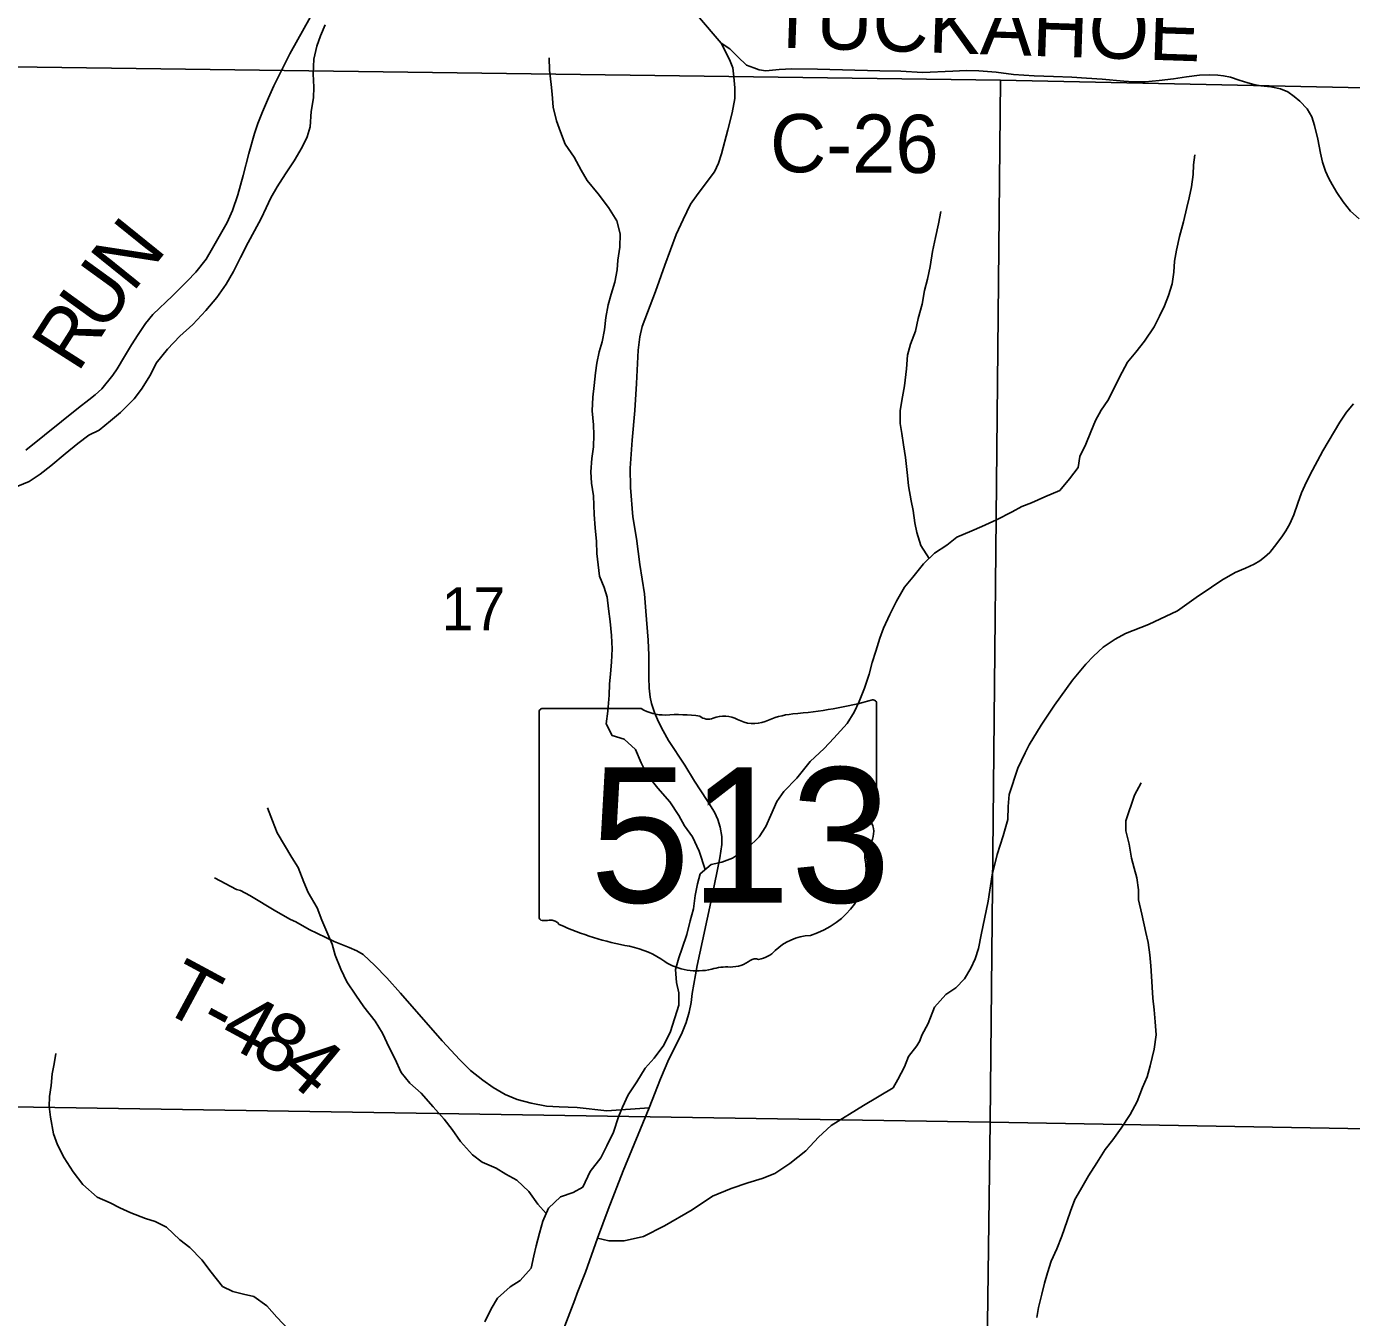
# Model space of a CAD drawing. Extents: x 0 to 191, y 0 to 55.
# Drawn here: x 148.062 to 148.709, y 23.985 to 24.615 of the extents above; entities that cross this region are included whole.
import ezdxf

# ---------------------------------------------------------------- set-up
doc = ezdxf.new("R2010")
doc.units = 0
for name, color, linetype in [('GM_X_Corporation', 7, 'Continuous'), ('GM_X_County_Road', 7, 'Continuous'), ('GM_X_County_Road_Text', 7, 'Continuous'), ('GM_X_Minor_River', 7, 'Continuous'), ('GM_X_Section_Text', 7, 'Continuous'), ('GM_X_State_Location', 7, 'Continuous'), ('GM_X_State_Route', 7, 'Continuous'), ('GM_X_State_Shield', 7, 'Continuous'), ('GM_X_Township_Road', 7, 'Continuous'), ('GM_X_Township_Road_Text', 7, 'Continuous')]:
    doc.layers.add(name, color=color, linetype=linetype)

msp = doc.modelspace()

# ---------------------------------------------------------------- linework, layer by layer
at = {"layer": 'GM_X_Corporation'}
for points in [[(148.03126, 24.59594), (148.53803, 24.58915), (148.53297, 24.08032), (148.0241, 24.08841)], [(148.53803, 24.58915), (149.0475, 24.57841), (149.03882, 24.07143), (148.53297, 24.08032)], [(148.0241, 24.08841), (148.53297, 24.08032), (148.52633, 23.57659), (148.01656, 23.58107)], [(148.53297, 24.08032), (149.03882, 24.07143), (149.03316, 23.56525), (148.52633, 23.57659)]]:
    msp.add_lwpolyline(points, close=True, dxfattribs=at)
at = {"layer": 'GM_X_County_Road'}
for points in [[(148.20115, 24.62009), (148.19102, 24.60199), (148.18321, 24.58628), (148.18065, 24.58049), (148.17763, 24.57367), (148.1754, 24.56792), (148.17374, 24.563), (148.17097, 24.55337), (148.16825, 24.54258), (148.16568, 24.5332), (148.16304, 24.52555), (148.16047, 24.51956), (148.15332, 24.50703), (148.15014, 24.50174), (148.14518, 24.49542), (148.14096, 24.49091), (148.13369, 24.48376), (148.1241, 24.47471), (148.12058, 24.47028), (148.11699, 24.46499), (148.11376, 24.45986), (148.11029, 24.45412), (148.10665, 24.44821), (148.10454, 24.44507), (148.09913, 24.43849), (148.09595, 24.43552), (148.09293, 24.43304), (148.08788, 24.42911), (148.07122, 24.4158), (148.06205, 24.40852)], [(148.40171, 24.60717), (148.40583, 24.60447), (148.40976, 24.6005), (148.41402, 24.59651), (148.41753, 24.59507), (148.42014, 24.5941), (148.42352, 24.59369), (148.42997, 24.59427), (148.4361, 24.59457), (148.44872, 24.59452), (148.4792, 24.59372), (148.48932, 24.59347), (148.49992, 24.59279), (148.51485, 24.59342), (148.52129, 24.59376), (148.52747, 24.59372), (148.53602, 24.593), (148.5444, 24.59194), (148.55457, 24.59126), (148.56392, 24.59097), (148.57294, 24.59059), (148.58009, 24.59012), (148.58763, 24.58965), (148.59822, 24.5886), (148.603, 24.5883), (148.60872, 24.58826), (148.61557, 24.58893), (148.62252, 24.58974), (148.62895, 24.59067), (148.63526, 24.59148), (148.64009, 24.59177), (148.64424, 24.5916), (148.64695, 24.59126), (148.65042, 24.5905), (148.65465, 24.58915), (148.65884, 24.58783), (148.66172, 24.58703), (148.66524, 24.58627), (148.67006, 24.58584), (148.6748, 24.58483), (148.67832, 24.58339), (148.68154, 24.58119), (148.68425, 24.57882), (148.6878, 24.57518), (148.69005, 24.57124), (148.69144, 24.567), (148.69305, 24.56031), (148.69424, 24.5535), (148.6953, 24.54901), (148.69682, 24.54465), (148.69834, 24.54118), (148.69995, 24.53809), (148.70232, 24.53432), (148.70533, 24.52966), (148.70897, 24.52517), (148.71325, 24.52136)]]:
    msp.add_lwpolyline(points, dxfattribs=at)
at = {"layer": 'GM_X_Minor_River'}
for points in [[(148.05816, 24.39089), (148.06365, 24.39319), (148.06915, 24.39682), (148.07426, 24.40083), (148.08126, 24.40674), (148.08751, 24.4117), (148.09281, 24.41571), (148.09793, 24.41819), (148.10342, 24.42277), (148.10834, 24.42678), (148.11497, 24.43345), (148.11856, 24.43821), (148.1229, 24.44525), (148.12573, 24.45096), (148.13122, 24.45782), (148.13728, 24.46411), (148.14371, 24.46983), (148.14995, 24.47669), (148.15544, 24.48298), (148.15998, 24.48945), (148.16357, 24.49574), (148.16696, 24.50259), (148.17074, 24.50982), (148.17376, 24.51553), (148.17697, 24.52162), (148.17942, 24.52676), (148.18169, 24.5317), (148.1849, 24.53703), (148.18887, 24.54332), (148.19321, 24.54979), (148.19699, 24.55645), (148.19944, 24.5614), (148.20095, 24.56635), (148.2015, 24.57376), (148.20262, 24.58041), (148.2028, 24.58573), (148.2024, 24.59219), (148.20276, 24.59941), (148.20426, 24.60568), (148.20596, 24.61082), (148.20822, 24.61615)], [(148.3939, 24.20374), (148.39084, 24.21263), (148.3876, 24.21965), (148.38379, 24.22514), (148.38093, 24.23008), (148.37655, 24.23671), (148.37065, 24.24353), (148.36551, 24.24997), (148.36265, 24.25585), (148.35978, 24.2623), (148.35427, 24.26742), (148.34838, 24.26911), (148.34552, 24.2748), (148.34626, 24.28107), (148.347, 24.28886), (148.34718, 24.29418), (148.34755, 24.29931), (148.3481, 24.30501), (148.34846, 24.31148), (148.34807, 24.31793), (148.34748, 24.32477), (148.3467, 24.33104), (148.34593, 24.33674), (148.34459, 24.34148), (148.3423, 24.34699), (148.34152, 24.35249), (148.34094, 24.358), (148.34074, 24.36389), (148.34015, 24.37054), (148.33956, 24.377), (148.33935, 24.38612), (148.33838, 24.39238), (148.33799, 24.39789), (148.33854, 24.40435), (148.33929, 24.41006), (148.33946, 24.41595), (148.33926, 24.42089), (148.33867, 24.42772), (148.33903, 24.43438), (148.33959, 24.44008), (148.34033, 24.44616), (148.34089, 24.45091), (148.34201, 24.45643), (148.34352, 24.46137), (148.34464, 24.46727), (148.34538, 24.47316), (148.3465, 24.47943), (148.34801, 24.48457), (148.3497, 24.49046), (148.35082, 24.49655), (148.35119, 24.5013), (148.35212, 24.50757), (148.3523, 24.51403), (148.35076, 24.52049), (148.34657, 24.52693), (148.34162, 24.53357), (148.33629, 24.5402), (148.33324, 24.54513), (148.32981, 24.55158), (148.32543, 24.55783), (148.32314, 24.5639), (148.32123, 24.56922), (148.31969, 24.57586), (148.31911, 24.58232), (148.31871, 24.58707), (148.31775, 24.59391), (148.31773, 24.59999)], [(148.31728, 24.0384), (148.32315, 24.04393), (148.32941, 24.04604), (148.33415, 24.04871), (148.33773, 24.05632), (148.34284, 24.06298), (148.34586, 24.06888), (148.34907, 24.07554), (148.35152, 24.08295), (148.3534, 24.08771), (148.35623, 24.0938), (148.36039, 24.10008), (148.36455, 24.10674), (148.3689, 24.11169), (148.37363, 24.11797), (148.37684, 24.12463), (148.38098, 24.13756), (148.38096, 24.14345), (148.37981, 24.14858), (148.37941, 24.15484), (148.38092, 24.16055), (148.38261, 24.1653), (148.38487, 24.17196), (148.38656, 24.17861), (148.38807, 24.1845), (148.389, 24.19097), (148.39012, 24.19667), (148.39144, 24.20161), (148.39674, 24.20619), (148.40205, 24.20735), (148.40717, 24.20926), (148.41455, 24.21422), (148.42023, 24.21975), (148.42344, 24.2247), (148.4259, 24.23022), (148.42891, 24.23688), (148.43232, 24.24183), (148.43856, 24.24831), (148.44518, 24.2565), (148.45199, 24.26279), (148.45672, 24.26793), (148.46316, 24.27498), (148.46656, 24.2805), (148.46901, 24.28583), (148.47165, 24.2923), (148.47391, 24.29915), (148.47541, 24.30485), (148.4771, 24.31037), (148.47917, 24.31665), (148.48087, 24.32159), (148.48408, 24.32825), (148.48728, 24.33472), (148.49125, 24.34157), (148.49522, 24.34653), (148.50052, 24.35301), (148.50582, 24.35815), (148.51188, 24.36216), (148.5168, 24.36598), (148.524, 24.36904), (148.52893, 24.37115), (148.53613, 24.3744), (148.54371, 24.37842), (148.54845, 24.3809), (148.55318, 24.38282), (148.55963, 24.38569), (148.56702, 24.38875), (148.57175, 24.39447), (148.57591, 24.39999), (148.57684, 24.40532), (148.57967, 24.41141), (148.58212, 24.41749), (148.58438, 24.42301), (148.58721, 24.42796), (148.59043, 24.43272), (148.59364, 24.43881), (148.59609, 24.44414), (148.60005, 24.45138), (148.60421, 24.45633), (148.60837, 24.46167), (148.6131, 24.46871), (148.61574, 24.47385), (148.61819, 24.47899), (148.62008, 24.48394), (148.62196, 24.48964), (148.6227, 24.49535), (148.62307, 24.50067), (148.624, 24.50618), (148.6255, 24.51284), (148.62738, 24.51987), (148.62907, 24.52691), (148.6302, 24.53166), (148.63132, 24.53699), (148.63207, 24.54307), (148.63224, 24.54782), (148.63299, 24.55258)], [(148.5032, 24.35562), (148.49917, 24.36193), (148.49725, 24.3682), (148.49629, 24.37294), (148.49533, 24.37902), (148.49437, 24.38377), (148.49321, 24.39099), (148.49262, 24.39611), (148.49165, 24.40485), (148.49069, 24.41112), (148.48991, 24.41663), (148.48914, 24.42156), (148.48912, 24.42783), (148.49025, 24.43449), (148.49118, 24.43981), (148.49211, 24.44818), (148.49266, 24.45483), (148.49416, 24.46015), (148.49661, 24.46662), (148.49792, 24.47271), (148.4998, 24.47974), (148.50092, 24.4864), (148.50243, 24.49191), (148.50374, 24.49819), (148.50486, 24.50541), (148.50636, 24.51226), (148.50786, 24.51891), (148.50898, 24.525)], [(148.61185, 24.15159), (148.61146, 24.15671), (148.61106, 24.16203), (148.6101, 24.16811), (148.60895, 24.17304), (148.60703, 24.18197), (148.60549, 24.18899), (148.60548, 24.19374), (148.6047, 24.19963), (148.60336, 24.20437), (148.60202, 24.20931), (148.60087, 24.21614), (148.59933, 24.2226), (148.59932, 24.22754), (148.60346, 24.24009), (148.60667, 24.24599)], [(148.31621, 24.03586), (148.31216, 24.04029), (148.30778, 24.04654), (148.30188, 24.05203), (148.29656, 24.05505), (148.29181, 24.05788), (148.28497, 24.0609), (148.28022, 24.0645), (148.27432, 24.07094), (148.27032, 24.07681), (148.26633, 24.08193), (148.261, 24.0878), (148.2551, 24.09462), (148.24959, 24.09935), (148.2454, 24.10465), (148.24235, 24.11148), (148.23949, 24.11679), (148.23624, 24.12381), (148.23262, 24.12968), (148.2271, 24.13669), (148.22329, 24.14238), (148.21891, 24.14883), (148.21586, 24.15508), (148.21319, 24.16191), (148.21166, 24.16723), (148.20956, 24.17216), (148.20669, 24.17899), (148.2044, 24.18506), (148.20002, 24.19245), (148.19792, 24.19758), (148.19505, 24.20479), (148.19201, 24.20953), (148.18476, 24.22166), (148.18247, 24.22754), (148.18018, 24.2338)], [(148.55572, 23.98503), (148.55666, 23.98997), (148.55816, 23.99643), (148.55948, 24.00175), (148.56098, 24.00688), (148.56287, 24.01258), (148.56551, 24.01848), (148.56796, 24.02476), (148.5706, 24.03217), (148.57229, 24.03692), (148.57437, 24.04263), (148.5772, 24.04739), (148.58098, 24.05423), (148.58514, 24.06052), (148.58911, 24.06699), (148.59289, 24.07175), (148.59705, 24.07746), (148.60139, 24.08412), (148.60479, 24.0904), (148.60743, 24.09724), (148.6097, 24.10257), (148.6112, 24.10789), (148.61308, 24.11607), (148.61401, 24.1231), (148.61361, 24.12937), (148.61303, 24.13525), (148.61244, 24.14095), (148.61205, 24.14627), (148.61185, 24.15159)], [(148.19031, 23.97913), (148.1846, 23.98519), (148.17984, 23.99068), (148.17338, 23.99522), (148.16844, 23.99634), (148.16313, 23.99765), (148.15819, 24.00011), (148.15267, 24.00712), (148.1481, 24.01318), (148.1422, 24.01924), (148.13726, 24.02302), (148.1308, 24.02908), (148.12529, 24.03191), (148.12054, 24.03341), (148.11332, 24.03605), (148.108, 24.0385), (148.10325, 24.04096), (148.09698, 24.04378), (148.08995, 24.05003), (148.08519, 24.05609), (148.08081, 24.06291), (148.07757, 24.06936), (148.07566, 24.07467), (148.07412, 24.08284), (148.07354, 24.08796), (148.07372, 24.0929), (148.07446, 24.09822), (148.07502, 24.10392), (148.07595, 24.10886), (148.0767, 24.11399)], [(148.2863, 23.98285), (148.28932, 23.98932), (148.29235, 23.99446), (148.2986, 23.99998), (148.30352, 24.00304), (148.30882, 24.00913), (148.31013, 24.01521), (148.31126, 24.01996), (148.31295, 24.02624), (148.31464, 24.03213), (148.31728, 24.0384)]]:
    msp.add_lwpolyline(points, dxfattribs=at)
at = {"layer": 'GM_X_State_Route'}
msp.add_lwpolyline([(148.32067, 23.96905), (148.32691, 23.98526), (148.33021, 23.99369), (148.33129, 23.99685), (148.33539, 24.00709), (148.34125, 24.0238), (148.34646, 24.03774), (148.35378, 24.05663), (148.36651, 24.08735), (148.372, 24.10152), (148.37612, 24.11108), (148.38087, 24.12044), (148.38266, 24.12422), (148.38458, 24.12903), (148.3861, 24.13405), (148.38699, 24.1388), (148.38747, 24.14313), (148.38988, 24.15682), (148.39256, 24.16885), (148.39717, 24.19004), (148.40095, 24.20943), (148.4015, 24.21267), (148.40192, 24.21597), (148.40205, 24.21989), (148.40123, 24.22443), (148.39999, 24.22821), (148.39841, 24.23179), (148.39476, 24.23743), (148.38864, 24.24692), (148.38383, 24.25476), (148.37599, 24.26679), (148.37337, 24.27147), (148.37097, 24.2758), (148.36911, 24.28041), (148.36766, 24.28474), (148.36705, 24.28791), (148.36649, 24.29224), (148.36629, 24.2974), (148.36636, 24.30833), (148.36601, 24.31563), (148.36478, 24.32986), (148.36423, 24.33825), (148.36189, 24.3527), (148.36024, 24.36528), (148.35845, 24.37587), (148.35735, 24.39025), (148.35728, 24.39974), (148.35824, 24.41336), (148.35948, 24.4278), (148.36031, 24.44107), (148.36106, 24.45731), (148.36189, 24.46384), (148.36306, 24.46879), (148.36952, 24.48585), (148.37413, 24.49885), (148.3797, 24.5137), (148.38314, 24.52106), (148.38665, 24.52856), (148.39043, 24.53385), (148.39841, 24.54438), (148.4004, 24.54857), (148.40178, 24.55318), (148.40494, 24.56487), (148.407, 24.5732), (148.40838, 24.58021), (148.40838, 24.58537), (148.4079, 24.5908), (148.40728, 24.59514), (148.40577, 24.59926), (148.40171, 24.60717), (148.39009, 24.62065)], dxfattribs=at)
at = {"layer": 'GM_X_State_Shield'}
for p, q in [((148.47758, 24.23249), (148.47758, 24.28483)), ((148.31279, 24.28063), (148.31279, 24.18057)), ((148.36267, 24.28236), (148.31441, 24.28236)), ((148.47756, 24.2325), (148.47758, 24.23249))]:
    msp.add_line(p, q, dxfattribs=at)
for centre, major_axis, start_param, end_param in [((148.41888, 24.41877), (0.17476, 0), 4.814394, 5.042369), ((148.47575, 24.28505), (0.00183, 0), 6.141152, 7.989035), ((148.31467, 24.28085), (0.00191, 0), 1.712693, 3.28349), ((148.37416, 24.29397), (0.01852, 0), 4.042523, 4.731795), ((148.3803, 24.22618), (0.06648, 0), 1.404758, 1.657858), ((148.39539, 24.28137), (0.00534, 0), 3.836095, 5.185415), ((148.40323, 24.2698), (0.01111, 0), 0.950623, 2.079405), ((148.41757, 24.28566), (0.01336, 0), 4.081561, 5.145723), ((148.44117, 24.25179), (0.03516, 0), 1.699011, 2.107814), ((148.47562, 24.23229), (0.00196, 0), 5.05454, 6.418171), ((148.47715, 24.22865), (0.00284, 0), 1.883978, 3.671073), ((148.45909, 24.22203), (0.01704, 0), 5.934695, 6.695948), ((148.48415, 24.21059), (0.0124, 0), 2.387724, 3.262537), ((148.42867, 24.20393), (0.04371, 0), 5.101752, 6.440018), ((148.31469, 24.18035), (0.00193, 0), 3.00124, 4.508301), ((148.31498, 24.19059), (0.0147, 0), 4.665946, 4.897461), ((148.31799, 24.1748), (0.0053, 0), 0.519207, 1.627899), ((148.3849, 24.2647), (0.1262, 0), 4.195997, 4.488961), ((148.4471, 24.15248), (0.02394, 0), 1.647645, 2.488434), ((148.34728, 24.13562), (0.03949, 0), 0.823519, 1.323587), ((148.41676, 24.17088), (0.01412, 0), 4.937069, 5.64225), ((148.38998, 24.1743), (0.02506, 0), 4.026481, 4.996735), ((148.40446, 24.13971), (0.02059, 0), 1.495662, 1.94098), ((148.40629, 24.16681), (0.01335, 0), 4.691044, 5.507374), ((148.41837, 24.15712), (0.00376, 0), 1.147584, 2.315152)]:
    msp.add_ellipse(centre, major_axis=major_axis, ratio=0.8, start_param=start_param, end_param=end_param, dxfattribs=at)
at = {"layer": 'GM_X_Township_Road'}
for points in [[(148.48559, 24.09721), (148.48789, 24.10116), (148.4911, 24.10741), (148.49315, 24.11242), (148.49726, 24.11768), (148.49866, 24.12007), (148.49964, 24.12294), (148.50269, 24.12853), (148.50589, 24.13651), (148.51132, 24.14267), (148.51628, 24.14603), (148.52042, 24.1504), (148.5235, 24.15555), (148.52567, 24.1601), (148.52732, 24.16525), (148.52856, 24.17178), (148.5321, 24.18824), (148.53394, 24.20107), (148.53638, 24.21105), (148.53928, 24.22025), (148.54162, 24.2282), (148.54176, 24.2345), (148.54226, 24.24029), (148.54649, 24.25317), (148.55004, 24.26076), (148.55201, 24.26466), (148.5579, 24.27414), (148.56443, 24.28402), (148.57316, 24.29616), (148.57969, 24.30407), (148.58346, 24.30789), (148.58825, 24.31235), (148.59409, 24.31619), (148.59905, 24.31892), (148.61036, 24.32343), (148.62457, 24.32996), (148.63368, 24.33649), (148.64108, 24.34155), (148.64609, 24.34504), (148.65271, 24.34872), (148.65777, 24.35088), (148.66186, 24.35286), (148.66467, 24.35451), (148.66692, 24.35626), (148.66954, 24.35847), (148.67189, 24.36136), (148.67538, 24.36619), (148.67741, 24.36909), (148.67938, 24.37254), (148.68131, 24.37686), (148.6832, 24.38252), (148.68509, 24.38767), (148.68665, 24.39125), (148.68913, 24.39631), (148.69548, 24.40822), (148.70371, 24.42211), (148.70697, 24.42698), (148.71038, 24.43103)], [(148.15417, 24.19973), (148.16494, 24.19398), (148.16689, 24.19341), (148.17142, 24.19099), (148.18413, 24.18337), (148.19142, 24.17933), (148.19401, 24.17827), (148.20041, 24.17447), (148.21272, 24.16864), (148.22, 24.16572), (148.22381, 24.1641), (148.22689, 24.16232), (148.23255, 24.1569), (148.23838, 24.1509), (148.2451, 24.14329), (148.26543, 24.12014), (148.27401, 24.11082), (148.27919, 24.10564), (148.28527, 24.10087), (148.29029, 24.0973), (148.29612, 24.09382), (148.30211, 24.09147), (148.30883, 24.08961), (148.31628, 24.08823), (148.32259, 24.08783), (148.33126, 24.08759), (148.34583, 24.08589), (148.36651, 24.08735)], [(148.34125, 24.0238), (148.34687, 24.02245), (148.35427, 24.02245), (148.36372, 24.02451), (148.374, 24.02985), (148.38756, 24.03766), (148.39743, 24.04423), (148.40647, 24.04793), (148.41469, 24.05081), (148.42168, 24.05287), (148.42784, 24.05533), (148.43524, 24.06026), (148.44305, 24.06643), (148.44921, 24.073), (148.45538, 24.07876), (148.4712, 24.0885), (148.48559, 24.09721)]]:
    msp.add_lwpolyline(points, dxfattribs=at)

# ---------------------------------------------------------------- texts
at = {"layer": 'GM_X_County_Road_Text'}
for s, height, rotation, p in [('TUCKAHOE', 0.028409, 358.12412, (148.42455, 24.60519)), ('C-26', 0.028409, 359.6571, (148.42544, 24.54423)), ('N', 0.02841, 51.12172, (148.11419, 24.48498)), ('U', 0.02841, 54.09475, (148.09977, 24.46504)), ('R', 0.02841, 57.49318, (148.08748, 24.44573))]:
    msp.add_text(s, height=height, rotation=rotation, dxfattribs=at).set_placement(p)
at = {"layer": 'GM_X_Section_Text'}
msp.add_text('17', height=0.020928, rotation=0.00001, dxfattribs=at).set_placement((148.26511, 24.32054))
at = {"layer": 'GM_X_State_Location'}
for s in ['s', 'r']:
    msp.add_text(s, height=0.0000947, dxfattribs=at).set_placement((148.39333, 24.22395))
msp.add_text('513', height=0.0000947, rotation=0.00001, dxfattribs=at).set_placement((148.3599, 24.21706))
at = {"layer": 'GM_X_State_Shield'}
msp.add_text('513', height=0.065918, dxfattribs=at).set_placement((148.33752, 24.18763))
at = {"layer": 'GM_X_Township_Road_Text'}
for s, rotation, p in [('T', 331.67342, (148.12651, 24.13601)), ('-', 331.67175, (148.14521, 24.12593)), ('4', 331.61008, (148.15548, 24.1204)), ('8', 331.37958, (148.17084, 24.11209)), ('4', 320.29904, (148.18501, 24.10452))]:
    msp.add_text(s, height=0.02841, rotation=rotation, dxfattribs=at).set_placement(p)

doc.saveas('drawing.dxf')
